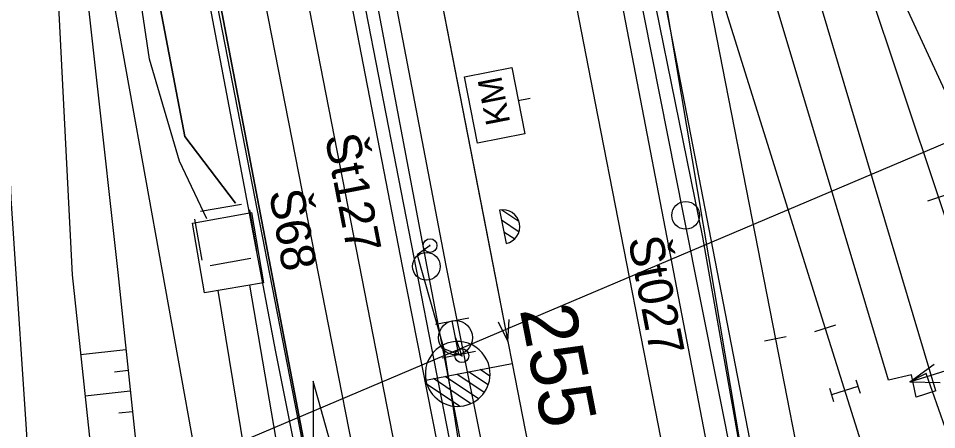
# Model space of a CAD drawing. Extents: x -545846 to -545044, y -1122650 to -1119108.
# Drawn here: x -545656.67 to -545623.48, y -1119606.96 to -1119592.1 of the extents above; entities that cross this region are included whole.
import ezdxf

# ---------------------------------------------------------------- set-up
doc = ezdxf.new("R2010")
doc.units = 0
for name, color, linetype in [('osvětlené plochy-hodnota-obrys', 7, 'Continuous'), ('Vrstva 1', 7, 'Continuous'), ('Vrstva 1 - Koleje', 7, 'Continuous'), ('Vrstva 19 - Staniceni', 7, 'Continuous'), ('Vrstva 2 - Vyhybky', 7, 'Continuous'), ('Vrstva 26', 7, 'Continuous'), ('Vrstva 27', 7, 'Continuous'), ('Vrstva 28 - zabzar', 7, 'Continuous'), ('Vrstva 3 - Lisy - Pocitaci body', 7, 'Continuous'), ('Vrstva 31', 7, 'Continuous'), ('Vrstva 32', 7, 'Continuous'), ('Vrstva 34', 7, 'Continuous'), ('Vrstva 35', 7, 'Continuous'), ('Vrstva 36', 7, 'Continuous'), ('Vrstva 4 - Teren - stezky - prechody - plochy', 7, 'Continuous'), ('Vrstva 43', 7, 'Continuous'), ('Vrstva 44', 7, 'Continuous'), ('Vrstva 48', 7, 'Continuous'), ('Vrstva 49', 7, 'Continuous'), ('Vrstva 63', 7, 'Continuous')]:
    doc.layers.add(name, color=color, linetype=linetype)

msp = doc.modelspace()

# ---------------------------------------------------------------- linework, layer by layer
at = {"layer": 'osvětlené plochy-hodnota-obrys'}
for points in [[(-545716.386, -1119223.717), (-545705.994, -1119221.66), (-545669.439, -1119408.759), (-545659.4, -1119462.635), (-545647.69, -1119521.347), (-545640.519, -1119558.729), (-545633.585, -1119589.698), (-545629.517, -1119613.814), (-545623.042, -1119645.057), (-545619.034, -1119667.556), (-545607.519, -1119727.517)], [(-545610.895, -1119760.665), (-545622.836, -1119699.488), (-545637.26, -1119626.872), (-545653.542, -1119543.449), (-545716.386, -1119223.717)], [(-545618.794, -1119749.17), (-545664.282, -1119515.639)]]:
    msp.add_lwpolyline(points, dxfattribs=at)
at = {"layer": 'Vrstva 1'}
msp.add_lwpolyline([(-545627.513, -1119603.305), (-545623.242, -1119616.862), (-545622.827, -1119618.168)], dxfattribs=at)
at = {"layer": 'Vrstva 1 - Koleje'}
for points in [[(-545673.811, -1119482.836), (-545671.313, -1119495.675), (-545669.505, -1119504.975), (-545667.947, -1119513.018), (-545662.4, -1119541.424), (-545660.697, -1119551.332), (-545659.275, -1119561.505), (-545658.148, -1119572.104), (-545657.527, -1119582.463), (-545657.339, -1119589.06), (-545656.945, -1119598.604), (-545656.274, -1119608.583), (-545655.31, -1119618.93), (-545654.021, -1119629.341), (-545652.534, -1119639.322), (-545651.124, -1119648.586), (-545649.453, -1119659.616), (-545647.771, -1119670.646), (-545646.146, -1119681.578), (-545645.086, -1119692.159), (-545644.623, -1119702.795), (-545644.886, -1119713.798)], [(-545670.736, -1119486.005), (-545668.403, -1119493.448), (-545665.355, -1119503.63), (-545662.43, -1119514.19), (-545659.814, -1119524.462), (-545657.519, -1119534.337), (-545655.38, -1119544.464), (-545653.502, -1119554.064), (-545651.433, -1119564.675), (-545649.38, -1119575.204), (-545647.23, -1119586.243), (-545645.16, -1119596.868), (-545643.254, -1119606.626), (-545640.837, -1119619.032)], [(-545661.358, -1119488.941), (-545659.379, -1119499.086), (-545658.213, -1119505.075), (-545656.26, -1119515.094), (-545654.191, -1119525.718), (-545653.022, -1119531.715), (-545652.764, -1119533.036), (-545651.421, -1119539.927), (-545649.507, -1119549.759), (-545647.011, -1119562.533), (-545642.802, -1119584.154), (-545639.767, -1119599.744), (-545638.981, -1119603.782), (-545638.828, -1119604.567)], [(-545653.037, -1119506.841), (-545652.888, -1119507.607), (-545649.059, -1119527.252), (-545646.668, -1119549.037), (-545645.204, -1119562.292), (-545642.802, -1119584.154), (-545638.981, -1119603.782), (-545638.828, -1119604.567)], [(-545653.037, -1119506.841), (-545652.888, -1119507.607), (-545652.099, -1119511.657), (-545649.059, -1119527.252), (-545644.851, -1119548.835), (-545643.914, -1119553.655), (-545642.404, -1119561.39), (-545639.909, -1119574.181), (-545637.584, -1119586.095), (-545635.82, -1119595.156), (-545633.965, -1119604.658), (-545632.137, -1119614.029), (-545631.264, -1119618.51), (-545629.612, -1119626.967), (-545629.361, -1119628.256), (-545628.203, -1119634.204), (-545626.651, -1119642.2), (-545624.573, -1119652.836), (-545622.753, -1119662.157), (-545621.579, -1119668.177), (-545619.497, -1119678.862), (-545617.408, -1119689.578), (-545615.292, -1119700.416), (-545613.256, -1119710.876)], [(-545633.918, -1119567.079), (-545633.672, -1119567.819), (-545628.667, -1119582.843), (-545621.718, -1119597.894), (-545620.45, -1119600.642), (-545619.123, -1119603.519)], [(-545633.918, -1119567.079), (-545633.672, -1119567.819), (-545628.667, -1119582.843), (-545623.418, -1119598.57), (-545620.367, -1119607.688), (-545618.295, -1119613.58)], [(-545635.682, -1119571.044), (-545635.531, -1119571.819), (-545632.499, -1119587.351), (-545627.516, -1119603.306)], [(-545635.682, -1119571.044), (-545635.531, -1119571.819), (-545634.862, -1119575.245), (-545632.499, -1119587.351), (-545629.31, -1119603.689), (-545628.19, -1119609.432), (-545627.412, -1119613.414), (-545625.512, -1119623.176), (-545623.669, -1119632.632), (-545622.964, -1119636.244), (-545621.873, -1119641.833), (-545619.406, -1119654.493), (-545617.375, -1119664.914), (-545615.537, -1119674.339), (-545613.73, -1119683.606), (-545613.194, -1119686.362), (-545611.288, -1119696.135), (-545609.289, -1119706.39), (-545607.258, -1119716.828)], [(-545638.828, -1119604.567), (-545636.749, -1119615.203), (-545635.189, -1119623.221), (-545634.427, -1119627.13)]]:
    msp.add_lwpolyline(points, dxfattribs=at)
at = {"layer": 'Vrstva 19 - Staniceni'}
msp.add_line((-545638.172, -1119594.994), (-545638.6, -1119595.078), dxfattribs=at)
msp.add_lwpolyline([(-545638.366, -1119596.274), (-545640.072, -1119596.607), (-545640.54, -1119594.211), (-545638.834, -1119593.878)], close=True, dxfattribs=at)
at = {"layer": 'Vrstva 2 - Vyhybky'}
for p, q in [((-545623.797, -1119598.696), (-545623.039, -1119598.444)), ((-545627.134, -1119603.187), (-545627.898, -1119603.425)), ((-545628.917, -1119603.612), (-545629.703, -1119603.766)), ((-545639.644, -1119604.728), (-545638.828, -1119604.567)), ((-545641.942, -1119605.175), (-545639.643, -1119604.728)), ((-545639.834, -1119605.619), (-545640.818, -1119604.956)), ((-545639.693, -1119605.348), (-545640.396, -1119604.875)), ((-545639.626, -1119605.026), (-545639.973, -1119604.792)), ((-545641.942, -1119605.176), (-545641.942, -1119605.175)), ((-545640.725, -1119606.119), (-545641.899, -1119605.327)), ((-545640.325, -1119606.022), (-545641.662, -1119605.12)), ((-545640.041, -1119605.846), (-545641.24, -1119605.038))]:
    msp.add_line(p, q, dxfattribs=at)
for points in [[(-545647.011, -1119562.533), (-545642.802, -1119584.154), (-545638.981, -1119603.782), (-545638.828, -1119604.567)], [(-545633.918, -1119567.079), (-545633.672, -1119567.819), (-545628.667, -1119582.843), (-545623.418, -1119598.57)], [(-545635.682, -1119571.044), (-545635.531, -1119571.819), (-545632.499, -1119587.351), (-545629.31, -1119603.689)], [(-545628.667, -1119582.843), (-545621.718, -1119597.894)], [(-545632.499, -1119587.351), (-545627.516, -1119603.306)], [(-545639.332, -1119603.063), (-545638.981, -1119603.782), (-545638.925, -1119602.984)]]:
    msp.add_lwpolyline(points, dxfattribs=at)
for centre, radius, start, end in [((-545640.792, -1119604.95), 1.17, 10.9479, 191.4174), ((-545640.792, -1119604.952), 1.171, 191.0374, 10.9982)]:
    msp.add_arc(centre, radius, start, end, dxfattribs=at)
at = {"layer": 'Vrstva 26'}
msp.add_lwpolyline([(-545648.815, -1119598.781), (-545650.646, -1119596.363), (-545652.517, -1119586.577), (-545654.036, -1119575.352), (-545654.599, -1119568.181), (-545656.827, -1119554.929), (-545656.997, -1119554.007), (-545657.467, -1119552.439), (-545664.456, -1119553.497), (-545667.067, -1119553.592), (-545667.602, -1119550.556), (-545667.729, -1119548.937), (-545668.467, -1119543.92), (-545670.355, -1119535.438), (-545673.845, -1119519.482), (-545676.203, -1119508.264), (-545678.142, -1119500.554), (-545680.197, -1119492.738), (-545680.794, -1119490.021), (-545681.126, -1119488.142)], dxfattribs=at)
at = {"layer": 'Vrstva 27'}
for p, q in [((-545641.785, -1119600.335), (-545641.795, -1119600.285)), ((-545640.635, -1119604.315), (-545640.645, -1119604.265))]:
    msp.add_line(p, q, dxfattribs=at)
for centre in [(-545641.79, -1119600.31), (-545640.64, -1119604.29)]:
    msp.add_circle(centre, 0.25, dxfattribs=at)
at = {"layer": 'Vrstva 28 - zabzar'}
for points in [[(-545629.8, -1119612.08), (-545631.93, -1119600), (-545634.62, -1119586.79), (-545636.82, -1119576.2), (-545637.62, -1119573.41), (-545638.67, -1119567.53), (-545639.49, -1119563.82), (-545639.85, -1119560.18), (-545641.01, -1119554.98), (-545644.07, -1119538.51), (-545646.66, -1119527.22), (-545647.144, -1119525.532), (-545647.46, -1119524.27), (-545648.47, -1119517.64), (-545649.03, -1119512.55), (-545649.84, -1119510.97), (-545650.5, -1119507.69), (-545650.68, -1119506.85), (-545651.64, -1119501.97), (-545654.86, -1119485.39)], [(-545649.855, -1119599.344), (-545650.84, -1119597.26), (-545651.93, -1119593.57), (-545654.86, -1119573.91), (-545655.08, -1119571.22), (-545656.42, -1119571.4), (-545660, -1119571.73), (-545661.56, -1119571.75), (-545664.78, -1119571.8), (-545665.2, -1119565.97), (-545667.1, -1119556.02), (-545671.77, -1119534.36), (-545673.21, -1119527.51), (-545675.52, -1119518.42), (-545676.6, -1119512.93), (-545677.33, -1119506.78), (-545681.37, -1119492.78), (-545681.68, -1119491.62), (-545683.99, -1119485.87)], [(-545641.79, -1119600.31), (-545642.25, -1119600.64), (-545641.29, -1119604.04), (-545640.39, -1119609.83), (-545638.26, -1119620.84), (-545636.71, -1119629.02), (-545635.93, -1119632.37), (-545634.08, -1119641.7), (-545634.3, -1119642.9), (-545639.59, -1119643.85), (-545640.12, -1119644.04), (-545640.107, -1119644.259)], [(-545640.87, -1119603.64), (-545640.64, -1119604.29), (-545641.29, -1119604.04)], [(-545602.41, -1119663.83), (-545602.8, -1119663.39), (-545603.89, -1119663.78), (-545604.71, -1119661.74), (-545605.8, -1119658.61), (-545607.17, -1119655.54), (-545608.43, -1119651.75), (-545609.58, -1119648.66), (-545612.26, -1119642.61), (-545614.17, -1119636.48), (-545616.81, -1119630.32), (-545617.94, -1119624.77), (-545618.68, -1119621.46), (-545618.67, -1119619.01), (-545619.98, -1119615.4), (-545621.7, -1119610.72), (-545623.18, -1119606.89), (-545623.86, -1119604.94), (-545624.45, -1119605.24)]]:
    msp.add_lwpolyline(points, dxfattribs=at)
at = {"layer": 'Vrstva 3 - Lisy - Pocitaci body'}
for p, q in [((-545639.279, -1119599.024), (-545639.044, -1119600.233)), ((-545639.196, -1119599.014), (-545638.586, -1119599.427)), ((-545639.21, -1119599.38), (-545638.575, -1119599.808)), ((-545639.126, -1119599.808), (-545638.732, -1119600.07)), ((-545639.044, -1119600.233), (-545639.044, -1119600.233)), ((-545641.592, -1119603.153), (-545640.383, -1119602.918)), ((-545640.752, -1119604.245), (-545640.988, -1119603.035)), ((-545641.357, -1119604.362), (-545640.148, -1119604.127)), ((-545624.45, -1119605.24), (-545623.567, -1119604.599)), ((-545624.45, -1119605.24), (-545623.134, -1119604.825)), ((-545626.401, -1119605.165), (-545626.252, -1119605.643)), ((-545624.45, -1119605.24), (-545623.359, -1119605.257)), ((-545627.356, -1119605.463), (-545627.207, -1119605.941)), ((-545626.327, -1119605.404), (-545627.281, -1119605.702))]:
    msp.add_line(p, q, dxfattribs=at)
msp.add_circle((-545640.871, -1119603.638), 0.616, dxfattribs=at)
for start, end in [(11.0067, 101.0067), (281.0067, 11.0067)]:
    msp.add_arc((-545639.161, -1119599.629), 0.616, start, end, dxfattribs=at)
at = {"layer": 'Vrstva 31'}
for points in [[(-545649.855, -1119599.344), (-545650.84, -1119597.26), (-545651.93, -1119593.57), (-545654.86, -1119573.91), (-545655.08, -1119571.22), (-545656.42, -1119571.4), (-545660, -1119571.73), (-545661.56, -1119571.75), (-545664.78, -1119571.8), (-545665.2, -1119565.97), (-545667.1, -1119556.02), (-545671.77, -1119534.36), (-545673.21, -1119527.51), (-545675.52, -1119518.42), (-545676.6, -1119512.93), (-545677.33, -1119506.78), (-545681.37, -1119492.78), (-545681.68, -1119491.62), (-545683.99, -1119485.87)], [(-545681.126, -1119488.142), (-545680.197, -1119492.738), (-545678.775, -1119498.148), (-545676.203, -1119508.264), (-545673.845, -1119519.482), (-545670.355, -1119535.438), (-545668.467, -1119543.92), (-545667.729, -1119548.937), (-545667.602, -1119550.556), (-545667.067, -1119553.592), (-545664.456, -1119553.497), (-545660.52, -1119553.11), (-545657.91, -1119552.94), (-545656.997, -1119554.007), (-545654.599, -1119568.181), (-545654.036, -1119575.352), (-545652.517, -1119586.577), (-545650.646, -1119596.363), (-545648.815, -1119598.781)], [(-545648.815, -1119598.781), (-545650.646, -1119596.363), (-545652.517, -1119586.577), (-545654.036, -1119575.352), (-545654.599, -1119568.181), (-545656.827, -1119554.929), (-545656.997, -1119554.007), (-545657.91, -1119552.94), (-545660.52, -1119553.11), (-545664.456, -1119553.497)]]:
    msp.add_lwpolyline(points, dxfattribs=at)
at = {"layer": 'Vrstva 32'}
msp.add_lwpolyline([(-545649.855, -1119599.344), (-545650.84, -1119597.26), (-545651.93, -1119593.57), (-545654.86, -1119573.91), (-545655.08, -1119571.22), (-545656.42, -1119571.4), (-545660, -1119571.73), (-545661.56, -1119571.75), (-545664.78, -1119571.8), (-545665.2, -1119565.97), (-545667.1, -1119556.02), (-545671.77, -1119534.36), (-545673.21, -1119527.51), (-545675.52, -1119518.42), (-545676.6, -1119512.93), (-545677.33, -1119506.78), (-545681.37, -1119492.78), (-545681.68, -1119491.62), (-545683.99, -1119485.87)], dxfattribs=at)
at = {"layer": 'Vrstva 34'}
for p, q in [((-545650.083, -1119599.069), (-545648.606, -1119598.809)), ((-545648.317, -1119599.013), (-545648.057, -1119600.49)), ((-545650.027, -1119600.835), (-545650.287, -1119599.358)), ((-545648.261, -1119600.779), (-545649.738, -1119601.039))]:
    msp.add_line(p, q, dxfattribs=at)
at = {"layer": 'Vrstva 35'}
for p, q in [((-545642.639, -1119643.278), (-545649.445, -1119601.934)), ((-545641.254, -1119643.012), (-545648.302, -1119601.738))]:
    msp.add_line(p, q, dxfattribs=at)
at = {"layer": 'Vrstva 36'}
for p, q in [((-545648.244, -1119599.109), (-545648.244, -1119599.109)), ((-545650.375, -1119599.494), (-545650.375, -1119599.494)), ((-545647.809, -1119601.653), (-545647.809, -1119601.653)), ((-545649.938, -1119602.019), (-545649.938, -1119602.019))]:
    msp.add_line(p, q, dxfattribs=at)
msp.add_lwpolyline([(-545650.375, -1119599.494), (-545648.244, -1119599.109), (-545647.809, -1119601.653), (-545649.938, -1119602.019)], close=True, dxfattribs=at)
msp.add_lwpolyline([(-545650.375, -1119599.494), (-545648.244, -1119599.109), (-545647.809, -1119601.653), (-545649.938, -1119602.019), (-545650.375, -1119599.494)], dxfattribs=at)
at = {"layer": 'Vrstva 4 - Teren - stezky - prechody - plochy'}
for points in [[(-545627.289, -1119622.488), (-545637.141, -1119571.643), (-545644.261, -1119535.203), (-545650.142, -1119505.011), (-545652.467, -1119492.497), (-545654.152, -1119492.935)], [(-545628.853, -1119622.763), (-545638.621, -1119571.934), (-545645.785, -1119535.614), (-545651.795, -1119505.293), (-545654.152, -1119492.935)], [(-545630.993, -1119656.823), (-545632.27, -1119648.758), (-545633.986, -1119638.317), (-545635.874, -1119627.618), (-545641.206, -1119601.036), (-545648.737, -1119561.68), (-545660.263, -1119502.835), (-545661.421, -1119496.666)], [(-545630.993, -1119656.823), (-545631.879, -1119657.017), (-545637.587, -1119627.431), (-545642.784, -1119601.05), (-545650.341, -1119562.037), (-545654.864, -1119538.891), (-545658.993, -1119521.274), (-545660.867, -1119513.982), (-545663.726, -1119503.551), (-545665.454, -1119497.849)], [(-545668.116, -1119499.514), (-545669.067, -1119499.733), (-545667.149, -1119508.296), (-545664.169, -1119519.775), (-545660.463, -1119535.199), (-545657.369, -1119550.681), (-545650.63, -1119584.9), (-545650.137, -1119587.57), (-545643.597, -1119621.824), (-545639.676, -1119641.733), (-545638.648, -1119646.558), (-545637.372, -1119653.536), (-545637.393, -1119653.539), (-545632.884, -1119675.451), (-545627.579, -1119703.177), (-545627.31, -1119704.719), (-545625.835, -1119712.063)], [(-545668.116, -1119499.514), (-545665.721, -1119507.929), (-545662.615, -1119519.622), (-545659.148, -1119534.332), (-545655.765, -1119550.675), (-545641.939, -1119621.169), (-545637.993, -1119641.248), (-545631.568, -1119675.037), (-545626.43, -1119701.616), (-545620.933, -1119729.23), (-545619.776, -1119736.256), (-545618.414, -1119746.042), (-545618.118, -1119750.155), (-545617.307, -1119763.323), (-545616.619, -1119772.592), (-545616.223, -1119779.957), (-545616.135, -1119786.617)], [(-545656.026, -1119569.241), (-545654.499, -1119571.456), (-545653.398, -1119574.472), (-545651.008, -1119584.887), (-545650.604, -1119587.134), (-545647.381, -1119604.145), (-545643.83, -1119621.835), (-545639.676, -1119641.733)], [(-545639.676, -1119641.733), (-545643.597, -1119621.824), (-545650.137, -1119587.57), (-545650.63, -1119584.9), (-545653.11, -1119573.498), (-545653.963, -1119570.966), (-545656.026, -1119569.241)], [(-545623.51, -1119605.555), (-545624.228, -1119605.785), (-545624.392, -1119604.982), (-545625.226, -1119605.173), (-545629.276, -1119591.613), (-545631.565, -1119582.258), (-545632.511, -1119578.885), (-545631.617, -1119578.652)], [(-545623.51, -1119605.555), (-545627.847, -1119590.999), (-545630.583, -1119581.864), (-545631.617, -1119578.652)]]:
    msp.add_lwpolyline(points, dxfattribs=at)
at = {"layer": 'Vrstva 43'}
for centre in [(-545632.552, -1119599.218), (-545641.921, -1119601.061)]:
    msp.add_circle(centre, 0.5, dxfattribs=at)
at = {"layer": 'Vrstva 44'}
for points in [[(-545622.746, -1119648.835), (-545632.623, -1119599.24), (-545640.335, -1119560.272)], [(-545632.322, -1119650.948), (-545641.9, -1119601.074), (-545649.267, -1119562.096), (-545649.25, -1119561.916)], [(-545654.9, -1119582.222), (-545645.965, -1119631.818), (-545637.145, -1119681.816), (-545629.836, -1119730.566), (-545626.416, -1119761.521), (-545622.849, -1119813.009), (-545619.592, -1119863.304), (-545618.858, -1119914.175), (-545618.881, -1119950.565), (-545618.715, -1119963.415), (-545629.02, -1119997.179)]]:
    msp.add_lwpolyline(points, dxfattribs=at)
at = {"layer": 'Vrstva 48'}
for p, q in [((-545652.782, -1119604.084), (-545654.418, -1119604.257)), ((-545652.703, -1119604.83), (-545653.194, -1119604.882)), ((-545652.624, -1119605.576), (-545654.259, -1119605.749)), ((-545652.546, -1119606.322), (-545653.036, -1119606.373))]:
    msp.add_line(p, q, dxfattribs=at)
at = {"layer": 'Vrstva 49'}
for points in [[(-545655.117, -1119579.257), (-545655.465, -1119586.681), (-545654.728, -1119601.362), (-545652.589, -1119621.359), (-545650.163, -1119640.071), (-545647.474, -1119659.033), (-545644.608, -1119679.124), (-545643.003, -1119694.436)], [(-545655.117, -1119579.257), (-545654.637, -1119587.147), (-545653.079, -1119601.278), (-545650.95, -1119621.407), (-545647.998, -1119639.764), (-545644.487, -1119662.372), (-545641.063, -1119679.985), (-545638.92, -1119699.386)], [(-545646.013, -1119605.212), (-545646.024, -1119609.713), (-545645.175, -1119613.461)], [(-545644.419, -1119613.276), (-545644.934, -1119609.079), (-545646.013, -1119605.212)]]:
    msp.add_lwpolyline(points, dxfattribs=at)
at = {"layer": 'Vrstva 63'}
msp.add_line((-545594.493, -1119584.444), (-545679.644, -1119620.554), dxfattribs=at)

# ---------------------------------------------------------------- texts
at = {"layer": 'Vrstva 19 - Staniceni'}
msp.add_text('KM', height=0.8728, rotation=101.0465, dxfattribs=at).set_placement((-545638.889, -1119595.859))
at = {"layer": 'Vrstva 2 - Vyhybky'}
msp.add_text('255', height=2, rotation=281.0453, dxfattribs=at).set_placement((-545638.554, -1119602.625))
at = {"layer": 'Vrstva 34'}
msp.add_text('Š68', height=1.25, rotation=279.9453, dxfattribs=at).set_placement((-545647.614, -1119598.371))
at = {"layer": 'Vrstva 43'}
for s, p in [('Št127', (-545645.597, -1119596.372)), ('Št027', (-545634.641, -1119600.077))]:
    msp.add_text(s, height=1.25, rotation=280.9998, dxfattribs=at).set_placement(p)

doc.saveas('drawing.dxf')
